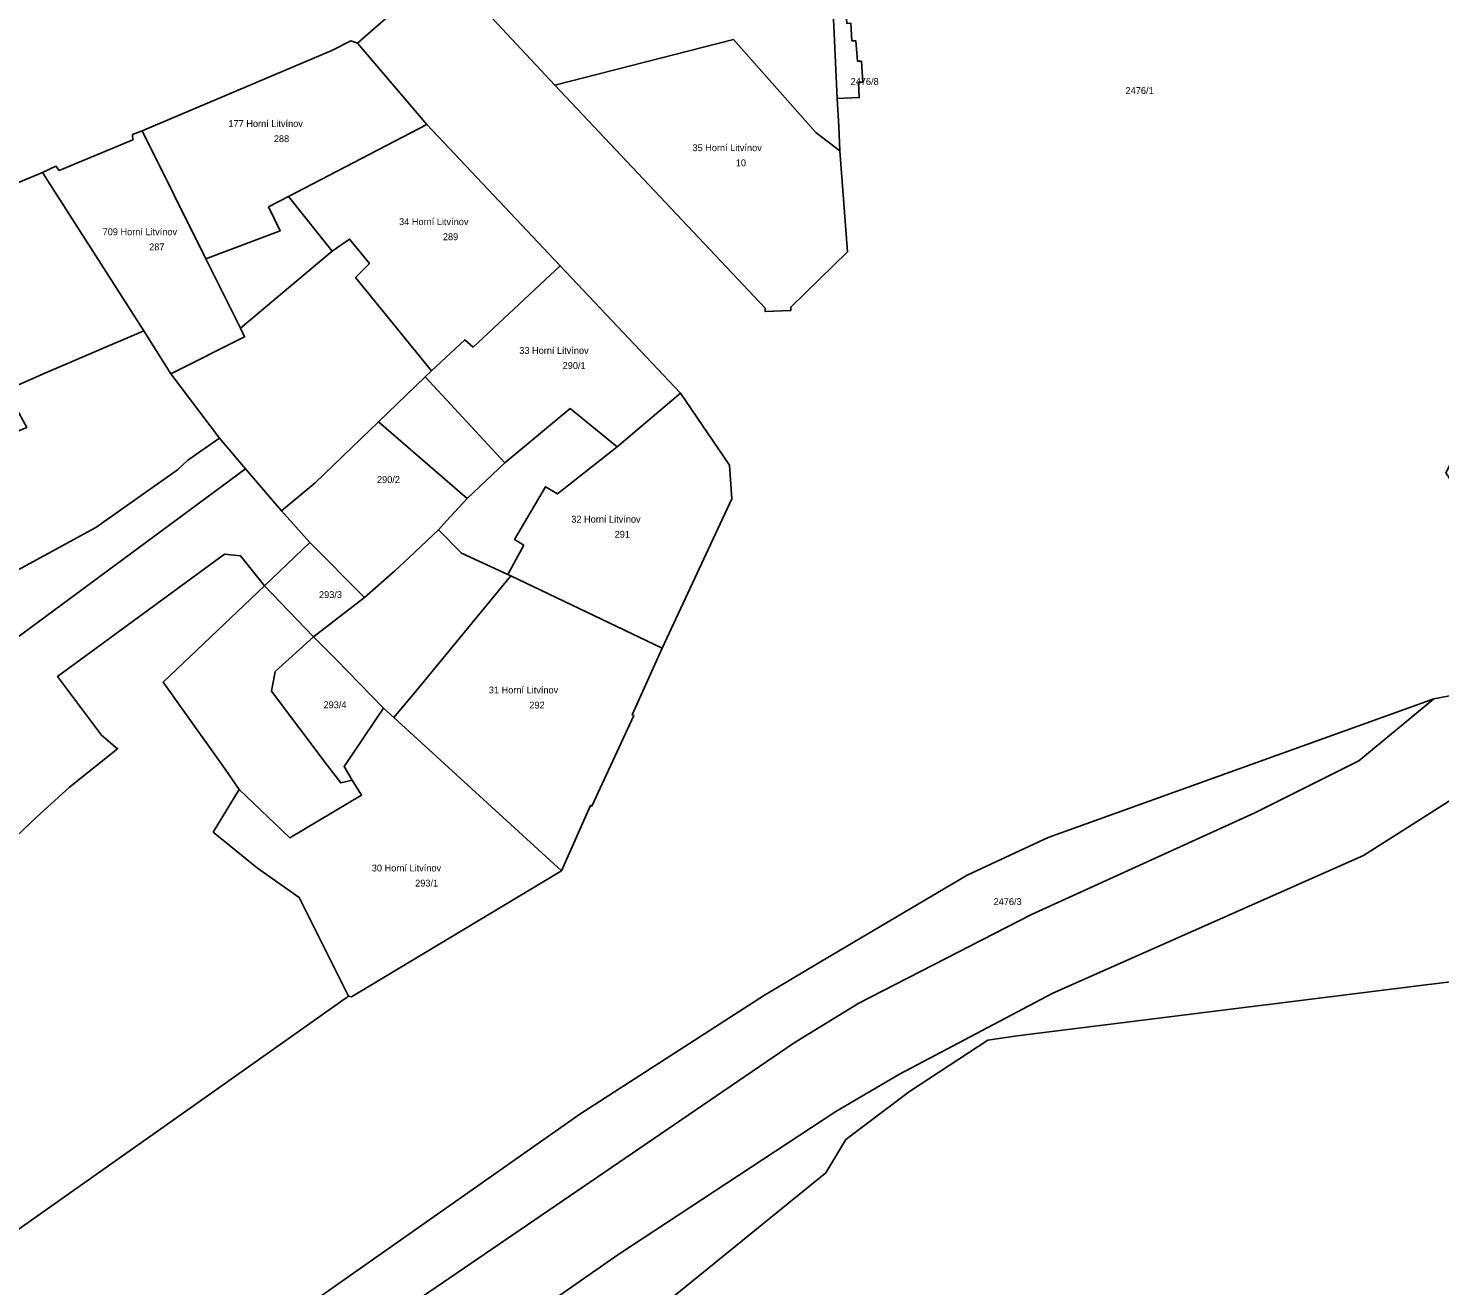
# Model space of a CAD drawing. Extents: x -792094 to -791524, y -979074 to -977761.
# Drawn here: x -791703.6 to -791600.7, y -978646.5 to -978554.8 of the extents above; entities that cross this region are included whole.
import ezdxf

# ---------------------------------------------------------------- set-up
doc = ezdxf.new("R2010")
doc.units = 0
doc.layers.add('katastr', color=7, linetype='Continuous')

msp = doc.modelspace()

# ---------------------------------------------------------------- linework, layer by layer
at = {"layer": 'katastr'}
for points in [[(-791747.66, -978693.14), (-791700.66, -978660.13), (-791696.13, -978657.01), (-791663.36, -978634), (-791649.9, -978625.34), (-791645.06, -978622.44), (-791635.14, -978616.59), (-791629.23, -978613.84), (-791601.12, -978603.73), (-791590.75, -978601.75), (-791600.26, -978587.26), (-791598.22, -978583.27), (-791596.85, -978581.78), (-791595.77, -978580.19), (-791594.51, -978564.55), (-791592.27, -978531.06)], [(-791717.3, -978571.49), (-791702.54, -978565.36), (-791701.56, -978564.9), (-791701.31, -978565.21), (-791695.94, -978562.98), (-791695.97, -978562.59), (-791695.28, -978562.32), (-791681.44, -978556.47), (-791680.06, -978555.76), (-791679.58, -978555.92), (-791678.41, -978554.9), (-791674.68, -978551.67)], [(-791674.68, -978551.67), (-791678.41, -978554.9), (-791679.58, -978555.92), (-791674.51, -978561.86), (-791664.79, -978572.15), (-791656.03, -978581.44), (-791652.46, -978586.69), (-791652.3, -978589.15), (-791657.37, -978600.04), (-791659.55, -978604.88), (-791659.44, -978604.93), (-791662.49, -978611.54), (-791662.6, -978611.49), (-791664.71, -978616.26), (-791680.02, -978625.44), (-791680.22, -978625.41), (-791691.02, -978633.03), (-791709.39, -978645.99)], [(-791643.61, -978554.47), (-791643.54, -978555.76), (-791643.24, -978555.76), (-791643.12, -978557.24), (-791642.84, -978557.24), (-791642.74, -978558.76), (-791643.06, -978558.77), (-791643, -978559.89), (-791644.6, -978559.97), (-791644.5, -978561.99), (-791644.41, -978563.77), (-791643.86, -978571.13), (-791648, -978575.17), (-791648, -978575.42), (-791649.87, -978575.49), (-791649.87, -978575.25), (-791665.2, -978559), (-791669.74, -978554.12)], [(-791704.5, -978613.82), (-791702.95, -978612.34), (-791700.59, -978610.19), (-791699.46, -978609.29), (-791697.06, -978607.36), (-791698.24, -978606.37), (-791701.43, -978602.09), (-791689.27, -978593.17), (-791688.1, -978593.31), (-791686.64, -978595.13), (-791686.35, -978595.49), (-791683.04, -978592.34), (-791685.12, -978590.03), (-791687.73, -978586.95), (-791704.49, -978599.34)], [(-791722.26, -978691.26), (-791696.26, -978672.29), (-791694.87, -978668.12), (-791690.45, -978665.09), (-791660.6, -978644.26), (-791644.7, -978633.82), (-791640.07, -978631.1), (-791628.89, -978625.18), (-791606.25, -978615.14), (-791597.45, -978609.56), (-791590.75, -978601.75), (-791601.12, -978603.73), (-791606.59, -978608.25), (-791614.16, -978612.03), (-791630.45, -978619.45), (-791643.04, -978625.92), (-791647.74, -978628.8), (-791693.82, -978660.25), (-791698.27, -978663.36), (-791700.66, -978660.13), (-791747.66, -978693.14)]]:
    msp.add_lwpolyline(points, dxfattribs=at)
for points in [[(-791644.6, -978559.97), (-791645.01, -978551.51), (-791645.22, -978547.25), (-791654.01, -978548.1), (-791655.81, -978548.1), (-791657.87, -978549.06), (-791669.74, -978554.12), (-791665.2, -978559), (-791652.17, -978555.67), (-791646.17, -978562.44), (-791644.41, -978563.77), (-791644.5, -978561.99)], [(-791669.74, -978554.12), (-791665.2, -978559), (-791652.17, -978555.67), (-791646.17, -978562.44), (-791644.41, -978563.77), (-791644.5, -978561.99), (-791644.6, -978559.97), (-791645.01, -978551.51), (-791645.22, -978547.25), (-791654.01, -978548.1), (-791655.81, -978548.1), (-791657.87, -978549.06)], [(-791643, -978559.89), (-791643.06, -978558.77), (-791642.74, -978558.76), (-791642.84, -978557.24), (-791643.12, -978557.24), (-791643.24, -978555.76), (-791643.54, -978555.76), (-791643.61, -978554.47), (-791643.91, -978554.49), (-791644.11, -978551.47), (-791645.01, -978551.51), (-791644.6, -978559.97)], [(-791679.58, -978555.92), (-791680.06, -978555.76), (-791681.44, -978556.47), (-791695.28, -978562.32), (-791690.63, -978571.65), (-791685.22, -978569.61), (-791686.06, -978567.86), (-791684.6, -978567.11), (-791674.51, -978561.86)], [(-791681.41, -978571.1), (-791684.6, -978567.11), (-791674.51, -978561.86), (-791679.58, -978555.92), (-791680.06, -978555.76), (-791681.44, -978556.47), (-791695.28, -978562.32), (-791690.63, -978571.65), (-791688.11, -978576.71)], [(-791652.17, -978555.67), (-791665.2, -978559), (-791649.87, -978575.25), (-791649.87, -978575.49), (-791648, -978575.42), (-791648, -978575.17), (-791643.86, -978571.13), (-791644.41, -978563.77), (-791646.17, -978562.44)], [(-791644.41, -978563.77), (-791646.17, -978562.44), (-791652.17, -978555.67), (-791665.2, -978559), (-791649.87, -978575.25), (-791649.87, -978575.49), (-791648, -978575.42), (-791648, -978575.17), (-791643.86, -978571.13)], [(-791674.51, -978561.86), (-791684.6, -978567.11), (-791681.41, -978571.1), (-791688.11, -978576.71), (-791687.8, -978577.34), (-791693.18, -978580.04), (-791689.62, -978584.72), (-791687.73, -978586.95), (-791685.12, -978590.03), (-791682.66, -978587.98), (-791678.05, -978583.53), (-791674.63, -978580.24), (-791674.17, -978579.81), (-791671.75, -978577.55), (-791671.14, -978578.08), (-791664.79, -978572.15)], [(-791674.51, -978561.86), (-791684.6, -978567.11), (-791681.41, -978571.1), (-791680.15, -978570.21), (-791678.7, -978572), (-791679.71, -978573.01), (-791674.17, -978579.81), (-791671.75, -978577.55), (-791671.14, -978578.08), (-791664.79, -978572.15)], [(-791702.54, -978565.36), (-791695.15, -978576.91), (-791693.18, -978580.04), (-791687.8, -978577.34), (-791688.11, -978576.71), (-791690.63, -978571.65), (-791695.28, -978562.32), (-791695.97, -978562.59), (-791695.94, -978562.98), (-791701.31, -978565.21), (-791701.56, -978564.9)], [(-791695.94, -978562.98), (-791701.31, -978565.21), (-791701.56, -978564.9), (-791702.54, -978565.36), (-791695.15, -978576.91), (-791693.18, -978580.04), (-791687.8, -978577.34), (-791688.11, -978576.71), (-791690.63, -978571.65), (-791695.28, -978562.32), (-791695.97, -978562.59)], [(-791702.54, -978565.36), (-791717.3, -978571.49), (-791712.49, -978584.39), (-791708.57, -978582.56), (-791708.03, -978583.65), (-791706.58, -978583.08), (-791705.84, -978584.81), (-791703.68, -978583.94), (-791705.16, -978581.22), (-791702.4, -978580.02), (-791699.02, -978578.54), (-791695.15, -978576.91)], [(-791691.93, -978586.33), (-791689.62, -978584.72), (-791693.18, -978580.04), (-791695.15, -978576.91), (-791702.54, -978565.36), (-791717.3, -978571.49), (-791712.49, -978584.39), (-791710.89, -978586.87), (-791706.46, -978595.5), (-791698.64, -978591.23), (-791692.7, -978587.03)], [(-791674.17, -978579.81), (-791674.63, -978580.24), (-791678.05, -978583.53), (-791671.58, -978589.13), (-791668.84, -978586.52), (-791664.07, -978582.57), (-791660.64, -978585.36), (-791656.03, -978581.44), (-791664.79, -978572.15), (-791671.14, -978578.08), (-791671.75, -978577.55)], [(-791674.17, -978579.81), (-791674.63, -978580.24), (-791668.84, -978586.52), (-791664.07, -978582.57), (-791660.64, -978585.36), (-791656.03, -978581.44), (-791664.79, -978572.15), (-791671.14, -978578.08), (-791671.75, -978577.55)], [(-791673.08, -978590.75), (-791673.67, -978591.4), (-791672, -978593.11), (-791668.61, -978594.67), (-791668.4, -978594.77), (-791657.37, -978600.04), (-791652.3, -978589.15), (-791652.46, -978586.69), (-791656.03, -978581.44), (-791660.64, -978585.36), (-791664.07, -978582.57), (-791668.84, -978586.52), (-791671.58, -978589.13)], [(-791667.45, -978592.52), (-791668.61, -978594.67), (-791668.4, -978594.77), (-791657.37, -978600.04), (-791652.3, -978589.15), (-791652.46, -978586.69), (-791656.03, -978581.44), (-791660.64, -978585.36), (-791664.99, -978588.78), (-791665.87, -978588.26), (-791668.12, -978592.1)], [(-791683.04, -978592.34), (-791679.07, -978596.35), (-791676.84, -978594.4), (-791675.81, -978593.43), (-791673.67, -978591.4), (-791673.08, -978590.75), (-791671.58, -978589.13), (-791678.05, -978583.53), (-791682.66, -978587.98), (-791685.12, -978590.03)], [(-791668.4, -978594.77), (-791668.61, -978594.67), (-791672, -978593.11), (-791673.67, -978591.4), (-791675.81, -978593.43), (-791676.84, -978594.4), (-791679.07, -978596.35), (-791682.77, -978599.21), (-791681.13, -978600.86), (-791679.42, -978602.61), (-791677.67, -978604.41), (-791676.93, -978605.09), (-791664.71, -978616.26), (-791662.6, -978611.49), (-791662.49, -978611.54), (-791659.44, -978604.93), (-791659.55, -978604.88), (-791657.37, -978600.04)], [(-791683.04, -978592.34), (-791686.35, -978595.49), (-791682.77, -978599.21), (-791679.07, -978596.35)], [(-791675.28, -978603.12), (-791676.93, -978605.09), (-791664.71, -978616.26), (-791662.6, -978611.49), (-791662.49, -978611.54), (-791659.44, -978604.93), (-791659.55, -978604.88), (-791657.37, -978600.04), (-791668.4, -978594.77)], [(-791689.23, -978608.86), (-791688.19, -978610.33), (-791684.5, -978613.87), (-791679.27, -978610.76), (-791679.96, -978609.66), (-791680.55, -978608.67), (-791677.67, -978604.41), (-791679.42, -978602.61), (-791681.13, -978600.86), (-791682.77, -978599.21), (-791686.35, -978595.49), (-791693.74, -978602.51)], [(-791690.09, -978613.44), (-791686.86, -978616.08), (-791683.82, -978618.2), (-791680.22, -978625.41), (-791680.02, -978625.44), (-791664.71, -978616.26), (-791676.93, -978605.09), (-791677.67, -978604.41), (-791679.42, -978602.61), (-791681.13, -978600.86), (-791682.77, -978599.21), (-791685.57, -978601.73), (-791685.85, -978603.17), (-791681.78, -978608.56), (-791680.8, -978609.86), (-791679.96, -978609.66), (-791679.27, -978610.76), (-791684.5, -978613.87), (-791688.19, -978610.33)], [(-791685.87, -978666.9), (-791677.61, -978664.41), (-791645.43, -978638.29), (-791643.99, -978635.86), (-791639.34, -978632.34), (-791633.62, -978628.61), (-791631.5, -978628.29), (-791595.45, -978623.8), (-791592.78, -978621.67), (-791590.87, -978619.03), (-791586.97, -978612.87), (-791579.87, -978610.17), (-791584.2, -978604.75), (-791590.75, -978601.75), (-791597.45, -978609.56), (-791606.25, -978615.14), (-791628.89, -978625.18), (-791640.07, -978631.1), (-791644.7, -978633.82), (-791660.6, -978644.26), (-791690.45, -978665.09), (-791689.23, -978666.85), (-791687.12, -978667.08)], [(-791696.13, -978657.01), (-791700.66, -978660.13), (-791698.27, -978663.36), (-791693.82, -978660.25), (-791647.74, -978628.8), (-791643.04, -978625.92), (-791630.45, -978619.45), (-791614.16, -978612.03), (-791606.59, -978608.25), (-791601.12, -978603.73), (-791629.23, -978613.84), (-791635.14, -978616.59), (-791645.06, -978622.44), (-791649.9, -978625.34), (-791663.36, -978634)], [(-791676.93, -978605.09), (-791677.67, -978604.41), (-791680.55, -978608.67), (-791679.96, -978609.66), (-791679.27, -978610.76), (-791684.5, -978613.87), (-791688.19, -978610.33), (-791690.09, -978613.44), (-791686.86, -978616.08), (-791683.82, -978618.2), (-791680.22, -978625.41), (-791680.02, -978625.44), (-791664.71, -978616.26)]]:
    msp.add_lwpolyline(points, close=True, dxfattribs=at)

# ---------------------------------------------------------------- texts
for s, p in [('2476/8', (-791643.63, -978558.97)), ('2476/1', (-791623.59, -978559.63)), ('177 Horní Litvínov', (-791688.98, -978562.04)), ('288', (-791685.67, -978563.14)), ('35 Horní Litvínov', (-791655.16, -978563.8)), ('10', (-791652, -978564.9)), ('34 Horní Litvínov', (-791676.54, -978569.19)), ('709 Horní Litvínov', (-791698.15, -978569.93)), ('289', (-791673.35, -978570.29)), ('287', (-791694.76, -978571.03)), ('33 Horní Litvínov', (-791667.78, -978578.58)), ('290/1', (-791664.62, -978579.68)), ('290/2', (-791678.15, -978587.99)), ('32 Horní Litvínov', (-791663.99, -978590.88)), ('291', (-791660.83, -978591.98)), ('293/3', (-791682.38, -978596.38)), ('31 Horní Litvínov', (-791670, -978603.33)), ('293/4', (-791682.05, -978604.41)), ('292', (-791667.05, -978604.43)), ('30 Horní Litvínov', (-791678.53, -978616.31)), ('293/1', (-791675.37, -978617.41)), ('2476/3', (-791633.21, -978618.76))]:
    msp.add_text(s, height=0.5, dxfattribs=at).set_placement(p)

doc.saveas('drawing.dxf')
